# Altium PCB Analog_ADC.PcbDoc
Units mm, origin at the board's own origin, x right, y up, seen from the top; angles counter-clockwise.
Board outline 78 x 60 mm, 4 copper layers (Top Layer, GND1, Power, Bottom Layer), stack 0.603 mm thick; 92 components, 48 nets, 281 pads, 215 vias.
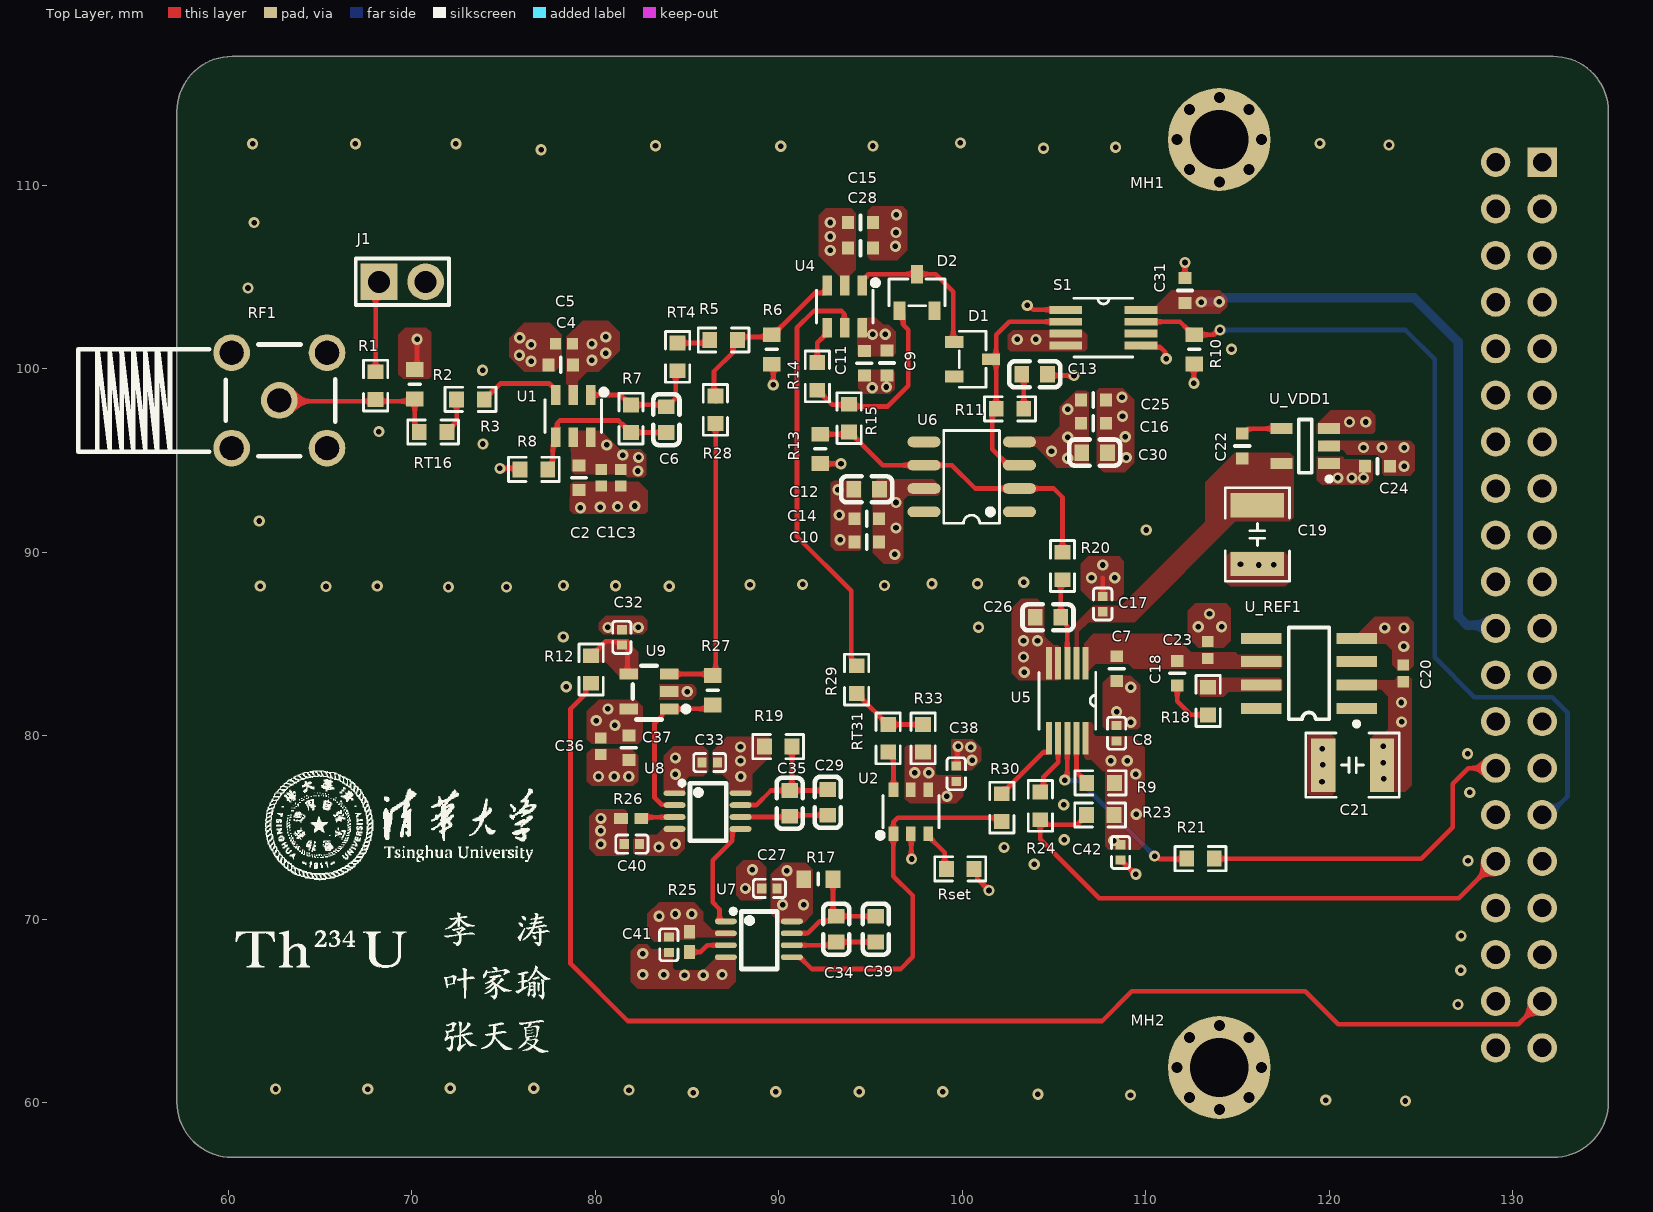
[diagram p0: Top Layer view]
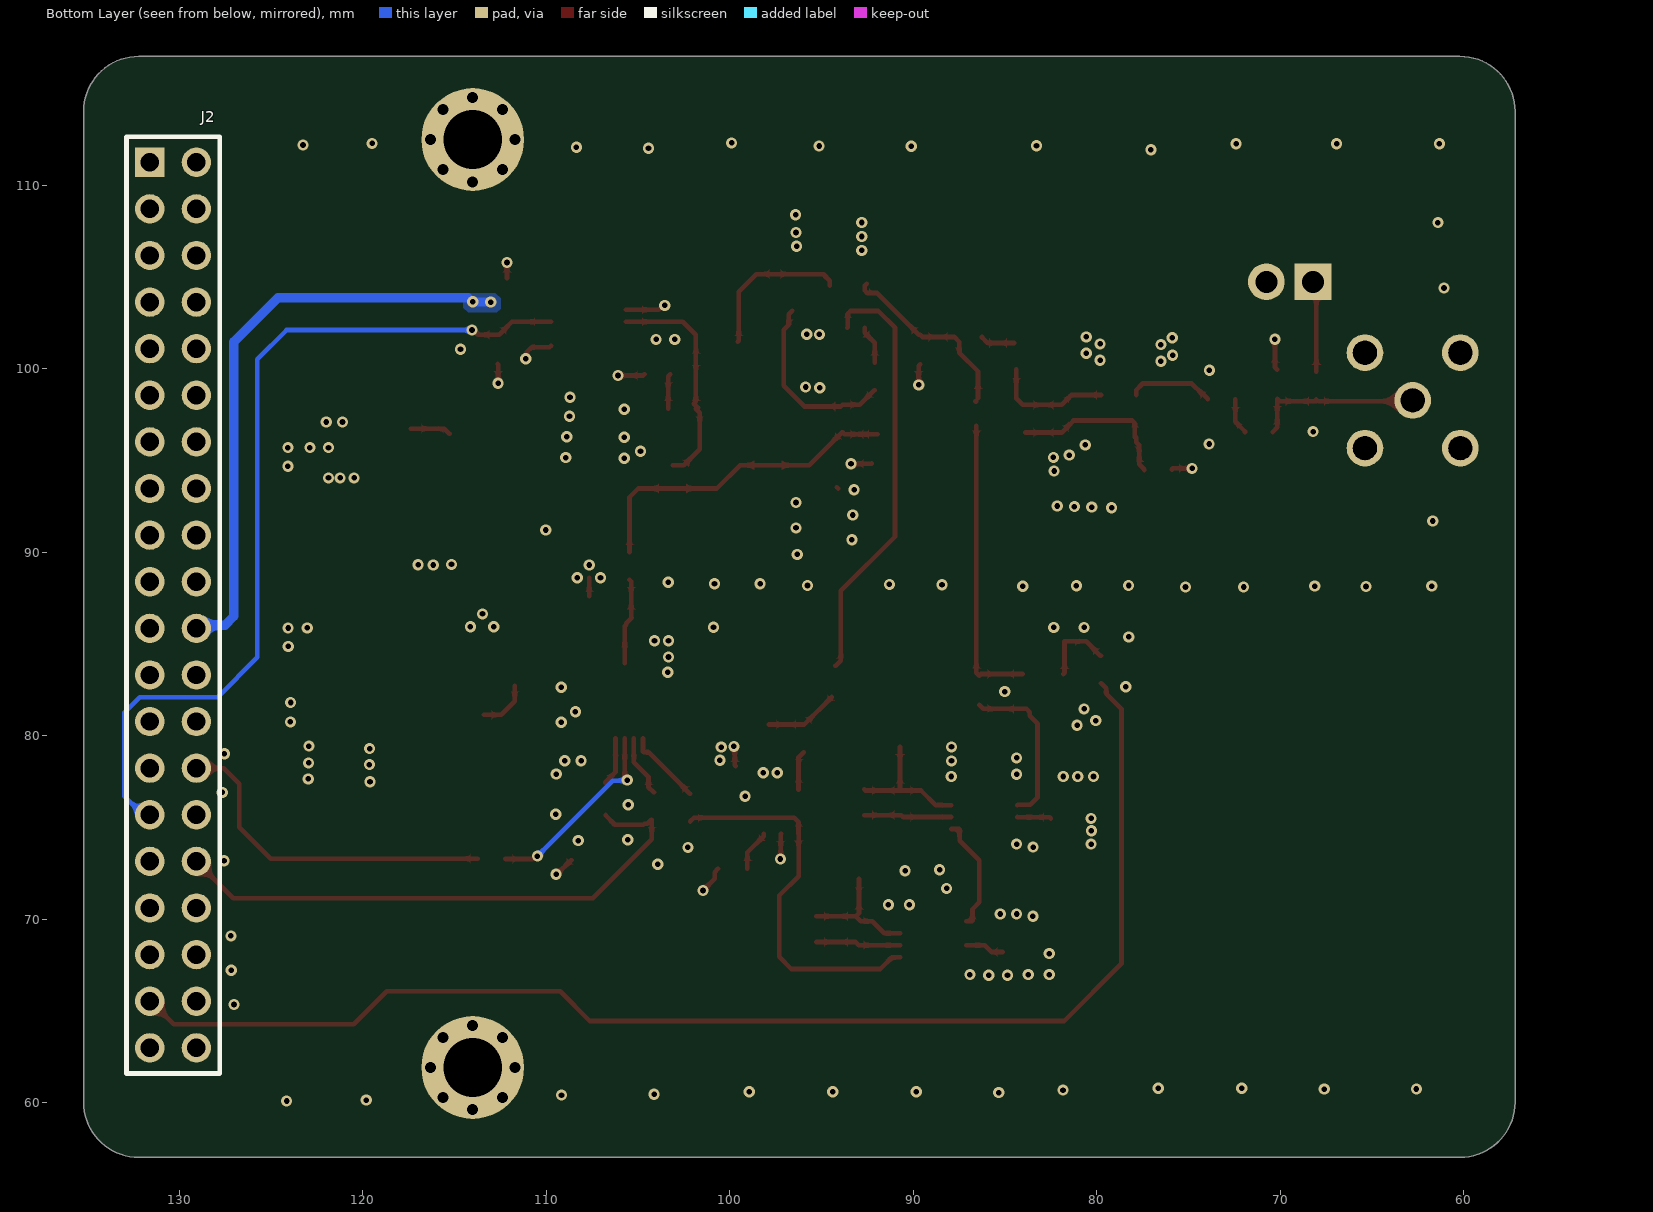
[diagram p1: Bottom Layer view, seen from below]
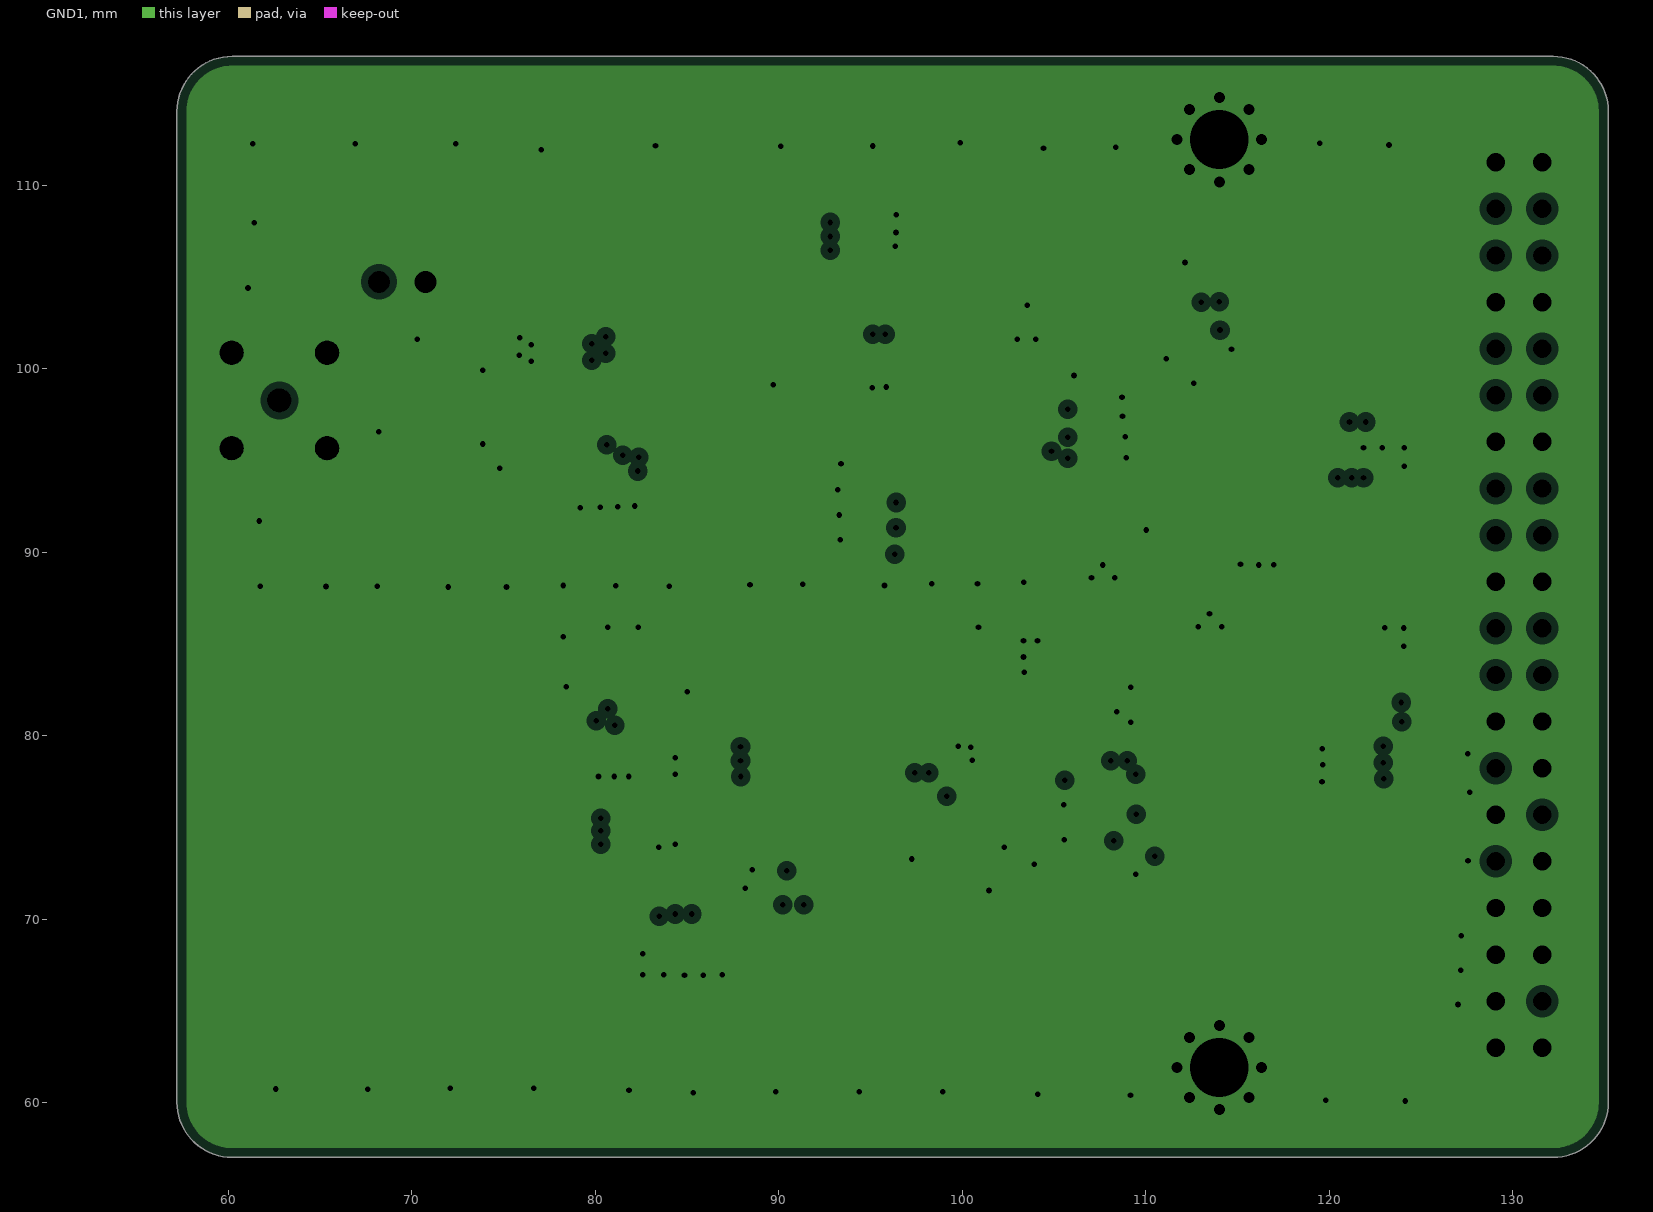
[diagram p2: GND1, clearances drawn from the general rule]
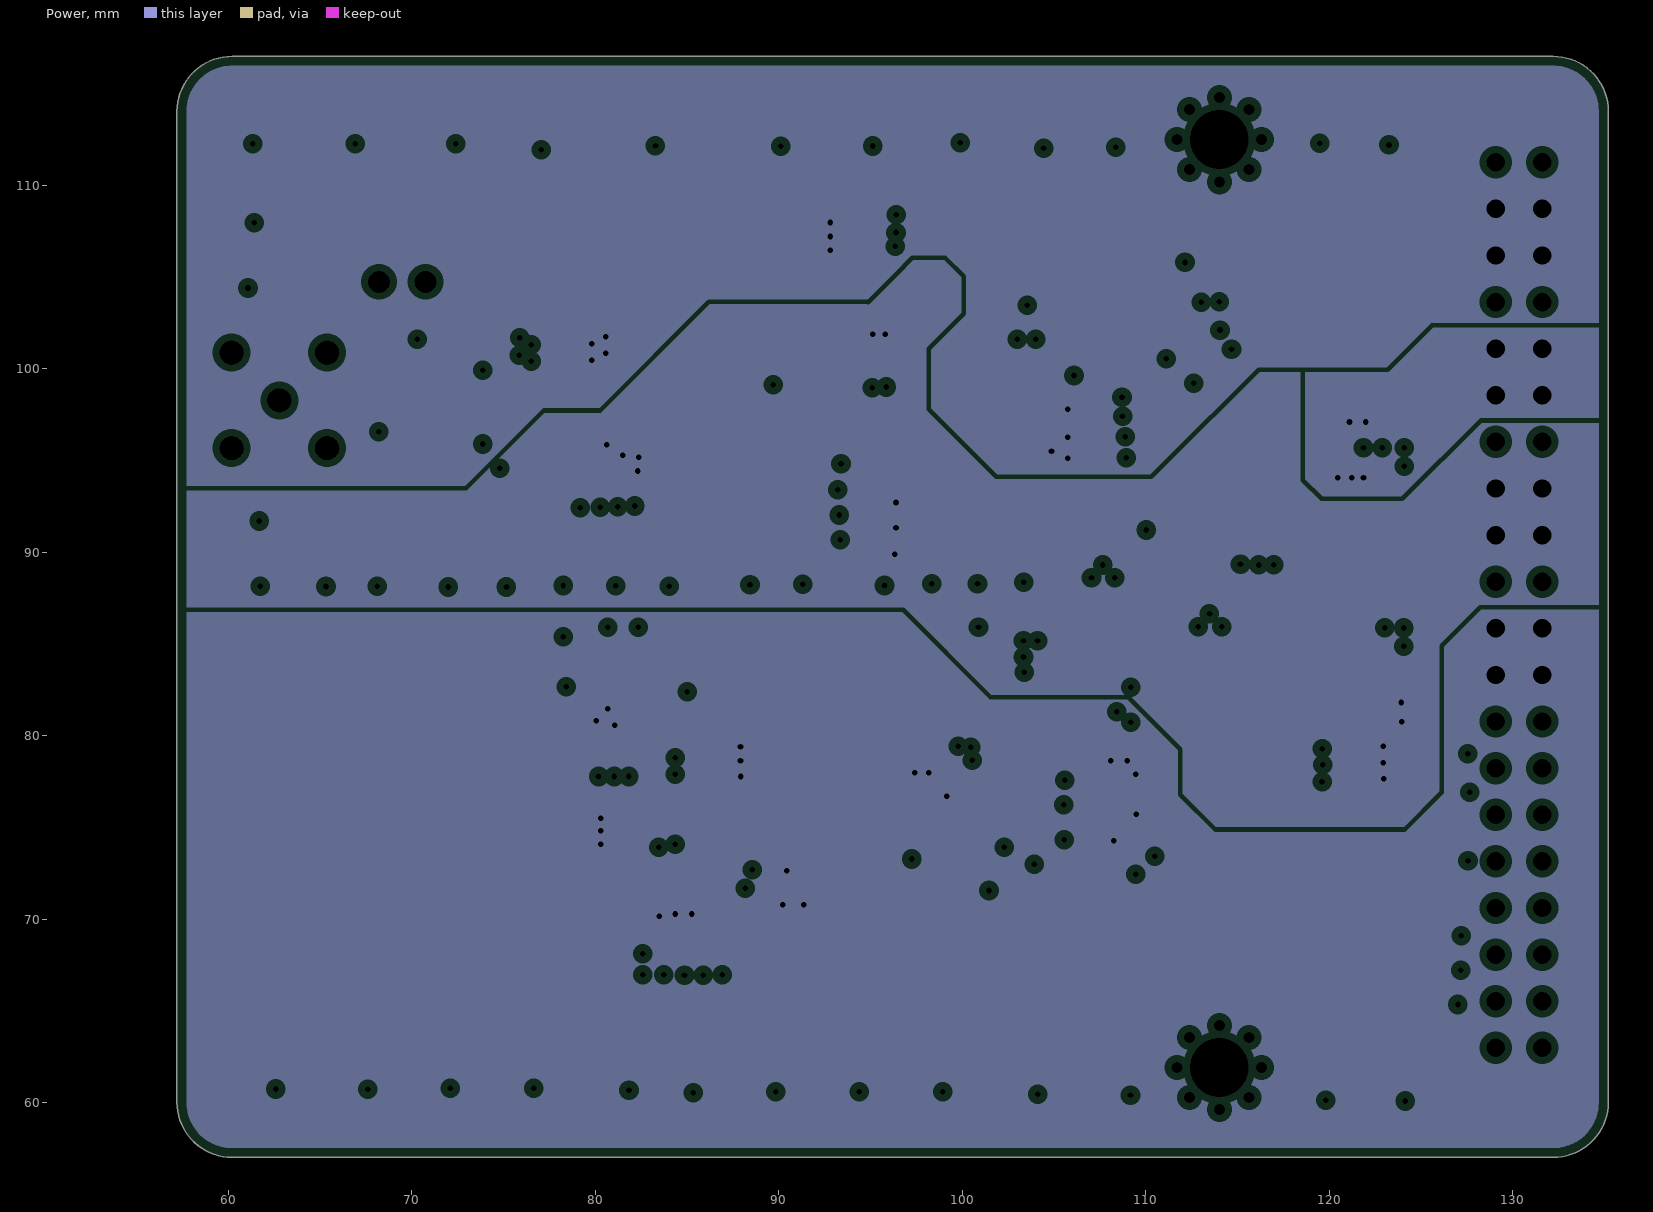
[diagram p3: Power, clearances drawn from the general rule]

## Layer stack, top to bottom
Top Solder: solder mask 0.0102, Solder Resist, Dk 3.5
Top Layer: signal copper 0.0356
Dielectric 2: prepreg 0.0711, PP-006, Dk 4.1
GND1: plane copper 0.035, net AGND
Dielectric 1: dielectric 0.32, FR-4, Dk 4.8
Power: plane copper 0.035, net (Multiple Nets)
Dielectric 3: prepreg 0.0711, PP-006, Dk 4.1
Bottom Layer: signal copper 0.0356
Bottom Solder: solder mask 0.0102, Solder Resist, Dk 3.5

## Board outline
57.207,60.023 57.207,114.023 cw(c60.207,114.023) 60.207,117.023 132.207,117.023 cw(c132.207,114.023) 135.207,114.023 135.207,60.023 cw(c132.207,60.023) 132.207,57.023 60.207,57.023 cw(c60.207,60.023)

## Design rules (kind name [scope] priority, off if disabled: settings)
Clearance [All] p1: gap=0.152 ignorepadtopadclearanceinfootprint=TRUE except(0: Arc-Hole Track-Hole SMDPad-Hole THPad-Hole Via-Hole Fill-Hole Poly-Hole Region-Hole Text-Hole)
HoleSize [All] p1: absolutevalues=TRUE maxlimit=12.7 minlimit=0.025 maxpercent=80.000 minpercent=20.000
HoleToHoleClearance [All] p1: gap=0 allowstackedmicrovias=TRUE
MinimumSolderMaskSliver [All] p1 off: minsoldermaskwidth=0
PlaneClearance [All] p1: clearance=0.381
PlaneConnect [All] p1: planeconnectstyle=Direct reliefexpansion=0.508 reliefentries=4 reliefconductorwidth=0.254 reliefairgap=0.254
PolygonConnect [All] p1: connectstyle=Direct reliefconductorwidth=0.254 reliefentries=4 polygonreliefangle="90 Angle" airgapwidth=0.254
RoutingVias [All] p1: holewidth=0.305 width=0.61 viastyle="Through Hole" minholewidth=0 minwidth=0 maxholewidth=2.54 maxwidth=2.54
SilkToSilkClearance [All] p1 off: silktosilkclearance=0
SilkToSolderMaskClearance [IsPad] p1 off: minsilkscreentomaskgap=0 clearancetoexposedcopper=TRUE
SolderMaskExpansion [All] p1: expansion=0.102 istentingtop=FALSE
Width [All] p1: maxlimit=0.762 minlimit=0.152 preferedwidth=0.254
23 further rules are at their usual default settings.

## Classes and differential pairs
component class Trigger: C27 C29 C32 C33 C34 C35 C36 C37 C38 C39 C40 C41 R12 R17 R19 R25 R26 R27 R28 R33 Rset RT31 U2 U7 U8 U9
component class Peakhold: C9 C10 C11 C12 C13 C14 C15 C16 C25 C28 C30 C31 D1 D2 R10 R11 R13 R14 R15 R29 S1 U4 U6
component class BAMP: C1 C2 C3 C4 C5 C6 R3 R5 R6 R7 R8 RT4 RT16 U1
component class Analog: C18 C19 C20 C21 C22 C23 C24 J1 J2 MH1 MH2 R1 R2 R18 RF1 U_REF1 U_VDD1
component class ADC: C7 C8 C17 C26 C42 R9 R20 R21 R23 R24 R30 U5

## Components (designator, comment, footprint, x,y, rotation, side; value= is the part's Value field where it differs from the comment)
C1 "1uF/50V" CAPC1005X70N 80.32,94.061 r90 top
C2 "100nF/100V" GRM18x 79.113,94.061 r270 top
C3 "1uF/50V" CAPC1005X70N 81.399,94.061 r90 top
C4 "100nF/100V" GRM18x 78.125,100.208 r0 top
C5 "1uF/50V" CAPC1005X70N 78.292,101.351 r0 top
C6 "15pF" C0603 83.955,97.233 r90 top
C7 "10uF/10V" GRM18x 108.418,83.655 r270 top
C8 "100nF" C0402 108.418,80.429 r270 top
C9 "1uF/25V" GRM18x 95.903,100.312 r270 top
C10 "4.7uF/25V" GRM18x 94.798,90.558 r180 top
C11 "100nF/100V" GRM18x 94.666,100.296 r270 top
C12 "470pF" C0603 94.798,93.352 r0 top
C13 "200pF" C0603 103.958,99.62 r0 top
C14 "100nF/100V" GRM18x 94.798,91.828 r180 top
C15 "1uF/25V" GRM18x 94.459,107.97 r180 top
C16 "100nF/100V" GRM18x 107.149,97.029 r180 top
C17 "100nF" C0402 107.656,86.881 r90 top
C18 "10nF/50V" GRM18x 111.72,83.401 r90 top
C19 "10uF 50V" C1210-H2r50 116.085,90.965 r270 top
C20 "100nF/50V" CAPC1005X70N 124.039,83.401 r90 top
C21 "10uF 50V" C1210-H2r50 121.271,78.4 r180 top
C22 "10nF/50V" GRM18x 115.264,95.786 r90 top
C23 "100nF/50V" CAPC1005X70N 113.371,84.671 r90 top
C24 "1uF/25V" GRM18x 122.63,94.683 r180 top
C25 "4.7uF/25V" GRM18x 107.149,98.299 r180 top
C26 "2.7nF" C0603 104.681,86.374 r0 top
C27 "100nF" C0402 89.197,71.682 r0 top
C28 "100nF/100V" GRM18x 94.459,106.573 r180 top
C29 "10pF，DNP" C0603 92.753,76.381 r90 top
C30 "470pF" C0603 107.212,95.505 r180 top
C31 "100nF/100V" GRM18x 112.141,104.267 r90 top
C32 "100nF" C0402 81.45,85.652 r270 top
C33 "100nF" C0402 85.946,78.54 r0 top
C34 "39pF NP0" C0603 93.21,69.465 r90 top
C35 "75pF" C0603 90.67,76.323 r90 top
C36 "1uF/50V" CAPC1005X70N 80.307,79.429 r90 top
C37 "100nF/100V" GRM18x 81.831,79.342 r270 top
C38 "100nF" C0402 99.674,78.221 r270 top
C39 "5pF, DNP" C0603 95.369,69.465 r90 top
C40 "100nF" C0402 81.704,74.095 r0 top
C41 "100nF" C0402 84.01,68.898 r270 top
C42 "100nF" C0402 108.63,73.348 r90 top
D1 "BAT17" SOT23-3 99.568,101.468 r180 top
D2 "BAT17" SOT23-3 96.586,103.157 r270 top
J1 "Header 2" "Header 2" 68.217,104.74 r0 top
J2 "PM2.54-2X20P-H85" "2*20 2.54mm 排母" 131.5,110.876 r270 bottom
MH1 "Mounting Hole (Screw)" MOUNT_PAD_L-M3 114.007,112.488 r0 top
MH2 "Mounting Hole (Screw)" MOUNT_PAD_L-M3 114.008,61.921 r0 top
R1 "50Ω" R0603 68.005,99.065 r270 top
R2 "1MΩ" RESC1608X55N 70.164,99.154 r270 top
R3 "22Ω" R0603 73.212,98.303 r0 top
R5 "50Ω" R0603 87.01,101.54 r0 top
R6 "1MΩ" RESC1608X55N 89.623,101.052 r90 top
R7 "470Ω" R0603 81.975,97.287 r90 top
R8 "470Ω" R0603 76.669,94.486 r0 top
R9 "0Ω" R0603 107.55,77.407 r0 top
R10 "100kΩ" RESC1608X55N 112.649,101.054 r270 top
R11 "22Ω" R0603 102.616,97.79 r0 top
R12 "1kΩ" R0603 79.799,83.62 r90 top
R13 "1MΩ" RESC1608X55N 92.26,95.637 r90 top
R14 "91Ω" R0603 92.075,99.568 r270 top
R15 "348Ω" R0603 93.813,97.295 r270 top
R17 "2kΩ" RESC1608X55N 92.156,72.19 r180 top
R18 "82kΩ" R0603 113.371,81.877 r270 top
R19 "5kΩ" R0603 89.959,79.429 r180 top
R20 "20Ω" R0603 105.491,89.262 r90 top
R21 "22Ω" R0603 112.996,73.278 r0 top
R23 "47kΩ" R0603 107.529,75.654 r0 top
R24 "22Ω" R0603 104.227,76.162 r270 top
R25 "10kΩ" RESC1005X35N 85.133,68.761 r90 top
R26 "10kΩ" RESC1005X35N 81.958,75.492 r0 top
R27 "100kΩ" RESC1608X55N 86.403,82.477 r270 top
R28 "100Ω" R0603 86.522,97.749 r270 top
R29 "50Ω" R0603 94.276,83.067 r90 top
R30 "22Ω" R0603 102.182,76.095 r90 top
R33 "47kΩ" R0603 97.896,79.872 r90 top
RF1 "HJ-SMA508" HJ-SMA508 59.931,102.911 r0 top
Rset "127kΩ" R0603 99.88,72.771 r180 top
RT4 "0Ω" R0603 84.516,100.657 r90 top
RT16 "0Ω" R0603 71.18,96.525 r0 top
RT31 "0Ω" R0603 95.991,79.872 r90 top
S1 "ADG721" RM_8 107.696,102.235 r0 top
U1 "ADA4807-1ARJZ-R2" ADA4807-1ARJZ-R2 80.491,98.947 r180 top
U2 "LTC6993-3" LTC6993-3 96.88,75.935 r270 top
U4 "ADA4807-1ARJZ-R2" ADA4807-1ARJZ-R2 95.29,104.91 r180 top
U5 "AD7980" MSOP-10 105.497,82.004 r0 top
U6 "THS4631DR" THS4631DR 101.526,92.215 r90 top
U7 "SN74LVC1G123DCTR" SSOP8 88.308,69.904 r180 top
U8 "SN74LVC1G123DCTR" SSOP8 85.514,76.889 r180 top
U9 "LMV7239QDBVRQ1" LMV7239QDBVRQ1 84.914,81.422 r0 top
U_REF1 "ADR431" SO-8 121.492,81.496 r180 top
U_VDD1 "LT1761ES5-2.5" SOT23-5 118.693,95.786 r180 top

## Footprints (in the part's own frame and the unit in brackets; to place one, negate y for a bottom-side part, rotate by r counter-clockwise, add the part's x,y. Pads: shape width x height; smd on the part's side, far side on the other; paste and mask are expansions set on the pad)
"2*20 2.54mm 排母" [mil]
  rect 63x63 hole 39.4: 1(-14.8,-4.2)
  round 63 hole 39.4: 2(-14.8,95.8) 3(85.2,-4.2) 4(85.2,95.8) 5(185.2,-4.2) 6(185.2,95.8) 7(285.2,-4.2) 8(285.2,95.8) 9(385.2,-4.2) 10(385.2,95.8) 11(485.2,-4.2) 12(485.2,95.8) 13(585.2,-4.2) 14(585.2,95.8) 15(685.2,-4.2) 16(685.2,95.8) 17(785.2,-4.2) 18(785.2,95.8) 19(885.2,-4.2) 20(885.2,95.8) 21(985.2,-4.2) 22(985.2,95.8) 23(1085.2,-4.2) 24(1085.2,95.8) 25(1185.2,-4.2) 26(1185.2,95.8) 27(1285.2,-4.2) 28(1285.2,95.8) 29(1385.2,-4.2) 30(1385.2,95.8) 31(1485.2,-4.2) 32(1485.2,95.8) 33(1585.2,-4.2) 34(1585.2,95.8) 35(1685.2,-4.2) 36(1685.2,95.8) 37(1785.2,-4.2) 38(1785.2,95.8) 39(1885.2,-4.2) 40(1885.2,95.8)
  silkscreen extent -70,-54 1940,146
ADA4807-1ARJZ-R2 [mm]
  rect 0.532x1.072 smd paste+0.051: 1(0.741,0.377) 2(1.691,0.377) 3(2.641,0.377) 4(2.641,2.675) 5(1.691,2.675) 6(0.741,2.675)
  silkscreen extent -0.13,0.07 3.23,2.42
C0402 [mil]
  rect 19.7x21.3 smd: 1(-5,0) 2(28,0)
  silkscreen extent -23,-20 46,20
C0603 [mm]
  rect 0.8x0.9 smd paste+0.051: 1(-0.707,0.075) 2(0.693,0.075)
  silkscreen extent -1.4,-0.64 1.38,0.79
C1210-H2r50 [mm]
  rect 1.321x2.921 smd paste+0 mask+0.076: 1(-1.6,0) 2(1.6,0)
  silkscreen extent -2.55,-1.75 2.55,1.75, body extent -1.6,-1.27 1.6,1.23, height 2.6
CAPC1005X70N [mm]
  rect 0.6x0.62 smd: 1(-0.46,0) 2(0.46,0)
  body extent -0.5,-0.25 0.5,0.25, height 0.5
GRM18x [mm]
  rect 0.65x0.7 smd: 1(-0.675,0) 2(0.675,0)
  silkscreen extent 0,-0.4 0,0.4, body extent -0.8,-0.45 0.8,0.45, height 0.8
"Header 2" [mm]
  rect 1.999x1.999 hole 1.199: 1(0,0)
  round 1.999 hole 1.199: 2(2.54,0)
  silkscreen extent -1.27,-1.27 3.81,1.27
HJ-SMA508 [mm]
  round 2 hole 1.3 slot 1.305 at 0 deg paste-2539.97 mask+0.051: 1(2.853,-4.637) 2(0.253,-2.037) 3(0.253,-7.237) 4(5.453,-7.237) 5(5.453,-2.037)
  silkscreen extent -8.1,-7.69 5.9,-1.59
LMV7239QDBVRQ1 [mm] "SOT23-5"
  rect 1.001x0.599 smd paste+0 mask+0.051: 1(-0.883,0.039) 2(-0.883,0.989) 3(-0.883,1.939) 4(-3.083,1.939) 5(-3.083,0.039)
  silkscreen extent -2.87,-0.54 0.18,2.39
LTC6993-3 [mil]
  rect 31.5x20.9 smd: 1(50.2,-24.74) 2(50.2,12.66) 3(50.2,50.06) 4(-44.3,50.06) 5(-44.3,12.66) 6(-44.3,-24.74)
  silkscreen extent -32,-59 60,73
MOUNT_PAD_L-M3 [mm]
  round 5.6 hole 3.2: 1(0,0)
MSOP-10 [mil]
  rect 13x70 smd: 1(48.37,76.5) 2(28.68,76.5) 3(9,76.5) 4(-10.69,76.5) 5(-30.37,76.5) 6(-30.37,-84.5) 7(-10.69,-84.5) 8(9,-84.5) 9(28.68,-84.5) 10(48.37,-84.5)
  silkscreen extent -52,-65 70,57, body extent -50,-105 68,88, height 45
R0603 [mm]
  rect 0.806x0.864 smd paste-100 mask+0.051: 1(-0.765,0.026) 2(0.741,0.026)
  silkscreen extent -1.4,-0.64 1.37,0.69
RESC1005X35N [mm]
  rect 0.75x0.6 smd: 1(-0.55,0) 2(0.55,0)
  body extent -0.5,-0.25 0.5,0.25, height 0.35
RESC1608X55N [mm]
  rect 0.8x0.95 smd: 1(-0.8,0) 2(0.8,0)
  silkscreen extent 0,-0.3 0,0.3, body extent -0.8,-0.4 0.8,0.4, height 0.55
RM_8 [mil]
  rect 70x17 smd mask+4: 1(-80.5,38.39) 2(-80.5,12.8) 3(-80.5,-12.8) 4(-80.5,-38.39) 5(80.5,-38.39) 6(80.5,-12.8) 7(80.5,12.8) 8(80.5,38.39)
  silkscreen extent -63,-63 63,63, body extent -102,-63 102,63, height 43
SO-8 [mm]
  rect 2.2x0.6 smd: 1(0,0) 2(0,-1.27) 3(0,-2.54) 4(0,-3.81) 5(5.2,-3.81) 6(5.2,-2.54) 7(5.2,-1.27) 8(5.2,0)
  silkscreen extent -0.12,-4.4 3.7,0.97, body extent -0.63,-4.42 5.71,0.58, height 1.88
SOT23-3 [mm]
  rect 1.001x0.65 smd: 1(0,0) 2(0,1.9) 3(-1.999,0.95)
  silkscreen extent -1.72,-0.58 -0.27,2.48
SOT23-5 [mm] "SOT23, for LT1964, 5-Leads, Body 2.9x2.8mm (max), Pitch 0.95mm, IPC Medium Density"
  rect 1.2x0.6 smd: 1(-1.3,0.95) 2(-1.3,0) 3(-1.3,-0.95) 4(1.3,-0.95) 5(1.3,0.95)
  silkscreen extent -1.43,-1.45 0.35,1.92, body extent -1.37,-1.46 0.97,1.46, height 1
SSOP8 [mm] "SN74"
  oval 1.196x0.315 smd: 1(1.189,0.021) 2(1.189,0.671) 3(1.189,1.321) 4(1.189,1.971) 5(-2.408,1.971) 6(-2.408,1.321) 7(-2.408,0.671) 8(-2.408,0.021)
  silkscreen extent -1.62,-0.66 0.91,2.62
THS4631DR [mil]
  oval 23.1x70.9 smd paste+0 mask+2: 1(-0.5,-62.6) 2(49.5,-62.6) 3(99.5,-62.6) 4(149.5,-62.6) 5(149.5,142.1) 6(99.5,142.1) 7(49.5,142.1) 8(-0.5,142.1)
  silkscreen extent -25,-20 174,100

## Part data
C1 C3 C5 C36: library part GRM155R61H105KE05D, "1uF 10% 50V 0402 X5R", Arrow Part Number=GRM155R61E105KA12D, Manufacturer_Name="Murata Electronics", Mouser Part Number=81-GRM155R61E105KA2D
C2 C4 C11 C14 C16 C28 C31 C37: library part GCM188R72A104KA64D, "100nF 10% 100V X7R 0603", Arrow Part Number=GRM188Z71A106KA73D, Manufacturer_Name="Murata Electronics", Mouser Part Number=81-GRM188Z71A106KA3D
C6: library part CC0603FRNPO9BN150, "15pF ±1% 50V 0603 NP0"
C7: library part GRM188Z71A106KA73D, "10uF 10% 10V X7R 0603", Manufacturer_Name="Murata Electronics", Mouser Part Number=81-GRM188Z71A106KA3D
C8 C17 C27 C32 C33 C38 C40 C41 C42: library part GCM155R71H104KE02D, "100nF ±10% 50V 0402 GCM"
C9 C15 C24: library part GCM188R71E105KA64D, "1uF 10% 25V X7R 0603", Arrow Part Number=GRM188Z71A106KA73D, Manufacturer_Name="Murata Electronics", Mouser Part Number=81-GRM188Z71A106KA3D
C10 C25: library part GRT188C81E475KE13D, "4.7uF 10% 25V 0603 X6S", Manufacturer_Name="Murata Electronics", Manufacturer_Part_Number=GRM155C71H683KE19D, Mouser Part Number=81-GRM155C71H683KE9D
C12 C30: library part CC0603KRX7R9BB471, "470pF ±10% 50V 0603 X7R"
C13: library part GCM1885C2A201FA16J, "200pF ±1% 100V 0603"
C18 C22: library part GCM1885C1H103GA16D, "10nF 2% 50V 0603 C0G", Manufacturer_Name="Murata Electronics", Manufacturer_Part_Number=GRM155C71H683KE19D, Mouser Part Number=81-GRM155C71H683KE9D
C19 C21: library part GRM32ER71H106KA12L, "10uF 50V 10% 1210 X7R"
C20 C23: library part GCM155R71H104KE02D, "100nF 10% 50V 0402 X7R", Manufacturer_Name="Murata Electronics", Manufacturer_Part_Number=GRM155C71H683KE19D, Mouser Part Number=81-GRM155C71H683KE9D
C26: library part CC0603KRX7R9BB272, "2.7nF ±10% 50V 0603 X7R"
C29: library part GCM1885C2A100FA16D, "10pF ±1% 100V 0603"
C34: library part CC0603JRNPO9BN390, "39pF ±5% 50V NP0"
C35: library part GQM1875C2E750FB12D, "75pF ±1% 250V 0603 C0G"
C39: library part GCM1885C1H5R0CA16D, "±0.25pF 5pF 50V 0603"
D1 D2: "电压:4V 电流:30mA"
J1: "1x2P 间距:2.54mm 方针 直插"
J2: "2*20 排母"
MH1 MH2: library part Mounting-Hole-Screw_1, "Mounting Hole, M3 Screw"
R1 R5 R29: library part RT0603BRE0750RL, "薄膜电阻 50Ω ±0.1% 100mW 0603"
R2 R6 R13: library part RT0603BRD071ML, "1MΩ 0.1% 0603 100mW 薄膜 25ppm/℃ 工作电压75V", Manufacturer_Name=YAGEO, Manufacturer_Part_Number=RT0603BRD07523KL
R3 R11 R21 R24 R30: library part RT0603BRE0722RL, "薄膜电阻 22Ω ±0.1% 100mW 0603"
R7 R8: library part RT0603BRB07470RL, "薄膜电阻 470Ω ±0.1% 100mW 0603"
R9 RT4 RT16 RT31: library part PMR03EZPJ000, "厚膜电阻 0Ω 250mW 0603"
R10 R27: library part RT0603BRD07100KL, "100kΩ 0.1% 0603 100mW 薄膜 25ppm/℃", Manufacturer_Name=YAGEO, Manufacturer_Part_Number=RT0603BRD07523KL
R12: library part RT0603BRD071KL, "薄膜电阻 1kΩ ±0.1% 100mW 0603"
R14: library part RT0603BRE0791RL, "薄膜电阻 91Ω ±0.1% 100mW 0603"
R15: library part TD03G3480BT, "薄膜电阻 348Ω ±0.1% 100mW 0603 FH"
R17: library part RT0603BRD072KL, "2kΩ 0.1% 0603 100mW 薄膜 25ppm/℃", Manufacturer_Name=YAGEO, Manufacturer_Part_Number=RT0603BRD07523KL
R18: library part RT0603BRD0782KL, "薄膜电阻 82kΩ ±0.1% 100mW 0603"
R19: library part RT0603BRE075KL, "薄膜电阻 5kΩ ±0.1% 100mW 0603"
R20: library part RT0603BRD0720RL, "薄膜电阻 20Ω ±0.1% 100mW 0603"
R23 R33: library part RT0603FRD0747KL, "薄膜电阻 47kΩ ±1% 100mW 0603"
R25 R26: library part RT0402BRD0710KL, "10kΩ 0.1% 0402 62.5mW 薄膜 25ppm/℃", Manufacturer_Name=YAGEO, Manufacturer_Part_Number=RT0402BRD07100RL, Mouser Part Number=603-RT0402BRD07100RL
R28: library part RT0603BRD07100RL, "薄膜电阻 100Ω ±0.1% 100mW"
Rset: library part RT0603DRE07127KL, "薄膜电阻 127kΩ ±0.5% 100mW 0603"
S1: library part ADG72x
U2: "下降沿触发单稳态触发器"
U5: "16-Bit, 1 MSPS PulSAR ADC in MSOP/QFN"
U6: "高压，高 slew rate，宽带 FET 输入运算放大器"
U7 U8: "单稳态多谐振荡器"
U_REF1: library part ADR43x
U_VDD1: library part LT1761-fix, "Low Noise LDO (100mA)-> 1.2~3.3V~5V, or Adj<20V"

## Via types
v1: diameter 0.61, hole 0.305, Top Layer to Bottom Layer, 199 vias
v2: diameter 1, hole 0.6, Top Layer to Bottom Layer, 16 vias

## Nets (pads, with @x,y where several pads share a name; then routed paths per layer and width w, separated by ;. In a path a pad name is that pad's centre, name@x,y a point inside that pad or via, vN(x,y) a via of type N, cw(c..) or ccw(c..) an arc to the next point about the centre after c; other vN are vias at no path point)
+2.5VA_REF: C7.1 C18.2 C23.1 U5.1 U_REF1.6
+2.5VA_VDD: C17.1 C19.1 C22.1 U5.2 U_VDD1.5
+3V3: C8.2 C27.2 C31.1 C33.2 C36.2 C37.1 C38.2 C40.1 C41.1 C42.2 J2.21 J2.22 J2.23 J2.24 R9.2 R17.2 R19.2 R23.2 R25.2 R26.1 R33.1 S1.8 U2.4 U2.5 U5.10 U7.2 U7.8 U8.8 U9.5 | length 32.4
  Bottom Layer w0.508: v1(113.03,103.632) v1@114.011,103.632 ; v1(114.011,103.648) 114.038,103.648 114.262,103.872 124.615,103.872 127.024,101.463 127.024,86.507 127.505,86.027 128.892,86.027 J2.22
  other v1: 83.482,70.158 84.371,70.285 85.26,70.285 90.213,70.793 91.356,70.793 90.443,72.643 80.307,74.095 108.259,74.285 80.295,74.82 80.307,75.492 109.482,75.716 99.166,76.697 87.927,77.778 109.454,77.911 97.417,77.987 98.179,77.987 87.915,78.63 108.102,78.631 108.991,78.631 87.915,79.392 81.069,80.572 80.053,80.826 80.688,81.461
+5V: C24.2 J2.9 J2.10 J2.11 J2.12 U_VDD1.1 U_VDD1.3
  other v1: 120.471,94.048 121.233,94.048 121.868,94.048 121.106,97.096 121.995,97.096
+5VA: C1.2 C2.1 C3.2 C9.1 C10.1 C11.1 C12.2 C14.1 C20.1 C21.1 J2.15 J2.16 J2.17 J2.18 U1.5 U1.6 U4.6 U6.7 U_REF1.2
  other v1: 122.968,77.645 122.949,78.519 122.936,79.434 123.947,80.755 123.93,81.81 96.32,89.883 96.392,91.326 96.393,92.71 82.323,94.426 82.365,95.167 81.501,95.295 80.625,95.848 95.117,101.869 95.803,101.875
-5VA: C4.2 C5.2 C15.2 C16.2 C25.2 C28.2 C30.2 J2.3 J2.4 J2.5 J2.6 U1.2 U4.2 U6.4
  other v1: 105.752,95.124 104.863,95.505 105.752,96.267 105.752,97.791 79.816,100.462 80.578,100.843 79.816,101.351 80.578,101.732 92.808,106.446 92.808,107.208 92.808,107.97
ADC_CNV: R30.1 U2.1 U7.5 | length 21
  Top Layer w0.254: U7.5 91.157,67.933 91.801,67.288 96.639,67.288 97.306,67.956 97.306,71.292 96.248,72.35 96.248,74.656 U2.1 96.251,75.293 96.493,75.535 101.951,75.535 R30.1
ADC_SCK: J2.28 R21.2 | length 18.8
  Top Layer w0.254: R21.2 125.01,73.304 126.726,75.02 126.726,77.389 127.569,78.232 J2.28
ADC_SDO: J2.32 R23.1 R24.2 | length 30.9
  Top Layer w0.254: R24.2 104.253,74.35 107.456,71.148 127.062,71.148 J2.32 ; R24.2@104.282,75.421 104.494,75.208 104.647,75.208 104.707,75.149 106.262,75.149 106.764,75.651 R23.1
AGND: C1.1 C2.2 C3.1 C4.1 C5.1 C7.2 C8.1 C9.2 C10.2 C11.2 C12.1 C13.2 C14.2 C15.1 C16.1 C17.2 C19.2 C20.2 C21.2 C23.2 C24.1 C25.1 C26.1 C27.1 C28.1 C30.1 C31.2 C32.1 C33.1 C36.1 C37.2 C38.1 C40.2 C41.2 C42.1 J1.2 J2.1 J2.2 J2.7 J2.8 J2.13 J2.14 J2.19 J2.20 J2.25 J2.26 J2.27 J2.30 J2.31 J2.33 J2.34 J2.35 J2.36 J2.38 J2.39 J2.40 MH1.1 MH2.1 R2.1 R6.1 R8.1 R10.2 R13.1 RF1.2 RF1.3 RF1.4 RF1.5 Rset.1 S1.1 S1.3 S1.4 S1.5 U2.2 U5.4 U5.5 U7.4 U8.1 U8.4 U9.2 U_REF1.4 U_VDD1.2 | length 19.8
  Top Layer w0.254: R2.1 70.291,100.081 v1(70.291,101.605) ; v1(74.806,94.568) 75.848,94.568 R8.1 ; R6.1 89.706,100.169 v1(89.706,99.118) ; R13.1 92.281,94.817 v1(93.394,94.817) ; C12.1@94.087,93.472 C12.1@94.162,93.547 ; U2.2 97.22,74.641 97.22,73.3 v1(97.238,73.281) ; C38.1 99.724,78.398 99.724,79.367 v1(99.774,79.417) ; Rset.1 100.827,72.563 100.827,72.198 v1(101.461,71.564) ; v1(103.547,103.451) 103.643,103.451 103.883,103.21 S1.1 ; C13.2 104.716,99.63 v1(106.091,99.63) ; 107.652,88.615 107.654,88.612 107.654,87.595 C17.2 ; C42.1 108.65,73.221 109.417,72.454 v1(109.466,72.454) ; S1.5 109.826,101.174 110.791,101.174 111.049,100.916 111.049,100.607 v1(111.117,100.539) ; C31.2 v1(112.141,105.791) ; v1(112.623,99.211) 112.623,100.228 R10.2 ; J2.30@128.843,75.468 J2.30
  Bottom Layer w0.254: J2.38@128.804,65.532 J2.38 ; J2.26@129.067,80.408 J2.26
  other v1: 124.148,60.093 119.811,60.142 109.169,60.414 104.122,60.46 85.34,60.551 89.842,60.596 94.39,60.596 98.937,60.596 81.839,60.687 62.579,60.749 67.6,60.744 72.102,60.79 76.649,60.79 127.015,65.354 84.867,66.946 85.883,66.946 82.593,66.983 83.736,66.983 86.911,66.983 127.169,67.223 82.593,68.126 127.188,69.089 88.181,71.682 88.562,72.698 103.921,72.995 127.562,73.183 102.285,73.915 83.47,73.931 84.371,74.095 105.562,74.327 105.536,76.233 127.661,76.913 119.609,77.495 80.18,77.778 81.035,77.778 81.831,77.778 84.371,77.905 119.637,78.425 100.541,78.668 84.371,78.794 127.539,79.021 119.628,79.298 100.46,79.379 109.18,80.734 108.413,81.311 85.017,82.404 109.18,82.639 78.423,82.668 103.379,83.461 103.338,84.29 124.058,84.869 103.338,85.179 104.1,85.179 78.257,85.388 123.022,85.878 124.07,85.869 80.688,85.906 82.339,85.906 100.886,85.911 112.863,85.941 114.133,85.941 113.473,86.639 71.999,88.106 75.163,88.106 65.327,88.131 84.031,88.148 61.746,88.152 68.119,88.156 81.107,88.168 78.265,88.188 95.765,88.188 88.436,88.229 91.299,88.249 98.349,88.282 100.831,88.282 103.357,88.36 107.045,88.608 108.315,88.608 107.655,89.306 116.164,89.306 115.166,89.335 116.983,89.321 93.345,90.678 110.032,91.21 61.69,91.701 93.302,92.03 79.191,92.427 80.274,92.461 81.221,92.483 82.158,92.517 93.225,93.404 124.078,94.683 108.938,95.154 121.868,95.699 122.884,95.699 124.078,95.699 73.879,95.897 108.882,96.292 68.213,96.571 108.736,97.41 108.707,98.442 95.093,98.963 95.87,99.006 73.864,99.914 76.506,100.403 75.87,100.732 114.676,101.062 76.506,101.316 102.997,101.6 104.013,101.6 75.885,101.689 61.078,104.398 96.356,106.675 96.392,107.421 61.407,107.963 96.414,108.394 77.052,111.93 104.431,112.013 108.359,112.066 90.11,112.119 83.282,112.151 95.135,112.136 123.258,112.194 61.328,112.262 66.93,112.262 72.41,112.262 119.494,112.279 99.899,112.304
  other v2: 114.008,59.621 112.382,60.294 115.634,60.294 111.708,61.921 116.308,61.921 112.382,63.547 115.634,63.547 114.008,64.221 114.007,110.188 112.381,110.862 115.634,110.862 111.707,112.488 116.307,112.488 112.381,114.115 115.634,114.115 114.007,114.788
NetC6_1: C6.1 R7.1 R8.2 U1.4 | length 9
  Top Layer w0.254: R8.2@77.411,94.483 R8.2 ; R8.2@77.413,94.526 77.689,94.802 77.689,95.841 77.85,96.001 U1.4 ; U1.4@77.926,96.271 77.926,97.028 78.075,97.177 81.266,97.177 81.92,96.522 83.877,96.522 C6.1
NetC6_2: C6.2 R7.2 RT4.1 U1.1 | length 6.6
  Top Layer w0.254: U1.1 81.38,98.57 81.92,98.029 R7.2 84.033,98.029 84.385,98.38 RT4.1@84.385,99.98
NetC13_1: C13.1 R11.2 | length 1.9
  Top Layer w0.254: C13.1 103.357,99.589 R11.2
NetC18_1: C18.1 R18.2 | length 2.8
  Top Layer w0.254: C18.1 111.72,81.877 112.462,81.136 R18.2
NetC22_2: C22.2 U_VDD1.4 | length 2.2
  Top Layer w0.254: C22.2 115.289,96.461 115.564,96.736 U_VDD1.4
NetC26_2: C26.2 R20.1 U5.3 | length 4.7
  Top Layer w0.254: C26.2@105.349,86.424 105.647,86.126 105.647,86.057 105.726,85.977 U5.3 ; C26.2 105.374,88.404 R20.1
NetC29_1: C29.1 C35.1 U8.6 | length 4.8
  Top Layer w0.254: U8.6 90.546,75.568 C35.1 90.652,75.674 C29.1
NetC29_2: C29.2 C35.2 R19.1 U8.7 | length 7.6
  Top Layer w0.254: U8.7 88.781,76.218 89.578,77.016 C35.2 ; R19.1 90.725,77.146 C35.2 ; C29.2 92.621,77.016 C35.2
NetC32_2: C32.2 R12.2 U9.4 | length 4.1
  Top Layer w0.254: R12.2 79.803,84.362 80.585,85.144 81.755,85.144 81.755,84.89 81.755,83.437 U9.4
NetC34_1: C34.1 C39.1 U7.6 | length 4.6
  Top Layer w0.254: U7.6 92.959,68.583 C34.1 C39.1
NetC34_2: C34.2 C39.2 R17.1 U7.7 | length 7.1
  Top Layer w0.254: U7.7 91.575,69.233 92.226,69.885 92.861,69.885 C34.2 ; R17.1 92.956,70.336 C34.2 ; C39.2 C34.2
NetD1_1: D1.1 D2.3 U4.1 | length 8.5
  Top Layer w0.254: U4.1 94.549,104.803 94.902,105.156 98.552,105.156 99.512,104.196 99.512,101.524 D1.1
NetD1_3: D1.3 R11.1 S1.2 U6.3 | length 12.4
  Top Layer w0.254: R11.1@101.727,97.865 101.764,97.902 101.957,98.095 101.849,98.204 101.849,100.518 101.849,101.153 101.849,101.849 102.56,102.56 S1.2 ; R11.1 101.636,97.601 101.636,95.615 102.509,94.742 U6.3
NetD2_1: D2.1 R14.2 R15.1 | length 10.1
  Top Layer w0.254: R14.2 92.129,98.827 92.912,98.044 93.853,98.044 93.953,97.944 95.942,97.944 97.064,99.066 97.064,102.113 96.784,102.393 96.784,102.959 D2.1
NetR3_1: R3.1 RT16.2 | length 2
  Top Layer w0.254: RT16.2 71.921,96.58 72.447,97.105 R3.1
NetR3_2: R3.2 U1.3 | length 4.7
  Top Layer w0.254: R3.2 73.953,98.358 74.229,98.634 74.258,98.634 74.817,99.192 77.497,99.192 77.85,98.84 U1.3
NetR5_1: R5.1 RT4.2 | length 1.9
  Top Layer w0.254: RT4.2 85.922,101.398 85.951,101.427 85.98,101.427 86.256,101.703 R5.1@86.256,101.732
NetR5_2: R5.2 R6.2 R28.1 U4.3 | length 10.3
  Top Layer w0.254: R28.1@86.474,98.385 86.474,99.866 87.487,100.879 87.487,101.456 87.763,101.732 89.503,101.732 R6.2 89.698,101.852 91.97,104.124 92.51,104.124 92.649,104.263 U4.3 U4.3@92.544,104.638 ; R28.1@86.585,98.204 R28.1@86.613,98.233
NetR9_1: R9.1 U5.9 | length 2.7
  Top Layer w0.254: U5.9 106.226,78.02 106.785,77.461 R9.1
NetR13_2: R13.2 R15.2 R20.2 U6.2 U6.6 | length 18
  Top Layer w0.254: R13.2@91.948,96.431 93.747,96.431 93.853,96.537 93.882,96.537 95.677,94.742 U6.6 99.441,94.742 100.711,93.472 U6.2 104.981,93.472 105.465,92.988 R20.2
NetR14_1: R14.1 U4.4 | length 2.1
  Top Layer w0.254: R14.1 92.101,101.417 92.649,101.965 U4.4
NetR18_1: R18.1 U_REF1.7
NetR21_1: R21.1 U5.8 | length 10.8
  Top Layer w0.254: v1(105.585,77.584) 105.585,77.68 105.726,77.82 U5.8 ; v1(110.482,73.44) 110.578,73.44 110.741,73.278 112.205,73.278 R21.1
  Bottom Layer w0.254: v1(105.585,77.584) 105.614,77.555 106.367,77.555 v1(110.482,73.44)
NetR24_1: R24.1 U5.7 | length 3.4
  Top Layer w0.254: R24.1@104.126,76.928 104.155,76.928 104.431,77.204 104.431,77.752 105.226,78.547 U5.7
NetR25_1: R25.1 U7.3 | length 2.1
  Top Layer w0.254: R25.1 85.726,68.211 86.098,68.583 U7.3
NetR26_2: R26.2 U8.3 | length 1.8
  Top Layer w0.254: R26.2 82.573,75.556 84.314,75.556 U8.3
NetR27_1: R27.1 R28.2 U9.3 | length 16.1
  Top Layer w0.254: U9.3 86.32,83.361 R27.1 86.562,83.436 R28.2@86.562,96.896
NetR29_1: R29.1 R33.2 RT31.2 | length 4
  Top Layer w0.254: R29.1@94.441,82.108 95.936,80.613 RT31.2 R33.2
NetR29_2: R29.2 U4.5 | length 23.6
  Top Layer w0.254: U4.5 93.57,102.264 93.57,102.997 93.422,103.145 91.901,103.145 90.992,102.236 90.992,90.856 93.945,87.903 93.945,84.085 94.221,83.809 R29.2
NetR30_2: R30.2 U5.6 | length 4.3
  Top Layer w0.254: R30.2 102.185,76.836 102.461,77.112 102.461,77.141 104.416,79.096 104.688,79.096 104.726,79.134 U5.6
NetRset_2: Rset.2 U2.3 | length 2.3
  Top Layer w0.254: U2.3 98.151,74.525 99.039,73.638 Rset.2@99.039,72.76
NetRT31_1: RT31.1 U2.6 | length 2.2
  Top Layer w0.254: RT31.1 95.975,79.106 96.251,78.83 U2.6
Q_DELAY: U7.1 U8.5 | length 6.4
  Top Layer w0.254: U7.1 86.801,69.884 86.773,69.912 86.773,70.551 86.403,70.92 86.403,73.206 87.472,74.274 87.472,74.89 87.5,74.918 U8.5
Restart: J2.29 R10.1 S1.7 | length 48.2
  Top Layer w0.254: S1.7 111.868,102.56 112.574,101.854 R10.1 113.696,101.854 113.95,102.108 v1(114.046,102.108)
  Bottom Layer w0.254: v1(114.046,102.108) 124.156,102.108 125.742,100.523 125.742,84.269 127.908,82.103 132.146,82.103 132.988,81.261 132.988,76.693 132.603,76.309 132.588,76.309 131.971,75.692 J2.29
Sig_in: R1.2 R2.2 RF1.1 RT16.1 | length 9
  Top Layer w0.254: RF1.1@63.162,98.226 67.932,98.226 R1.2 ; R1.2@68.03,98.226 70.035,98.226 R2.2 70.164,96.802 RT16.1
Threshold: J2.37 R12.1 | length 71.9
  Top Layer w0.254: R12.1 79.755,82.855 79.479,82.579 79.479,82.284 78.656,81.461 78.656,67.579 81.781,64.455 107.628,64.455 109.248,66.075 118.682,66.075 120.484,64.273 130.3,64.273 131.559,65.532 J2.37
TRIG_RAW: R27.2 U8.2 U9.1 | length 9
  Top Layer w0.254: U8.2 84.314,76.23 83.634,76.23 83.228,76.635 83.228,80.659 83.658,81.088 83.658,81.288 83.83,81.461 86.187,81.461 R27.2
Z50: J1.1 R1.1 | length 5.6
  Top Layer w0.254: J1.1@67.608,104.13 J1.1 ; R1.1 J1.1@68.03,104.552
pads on no net: D1.2 D2.2 S1.6 U6.1 U6.5 U6.8 U_REF1.1 U_REF1.3 U_REF1.5 U_REF1.8

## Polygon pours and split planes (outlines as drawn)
AGND on Top Layer "AGND_L01_P084" (solid, remove dead copper, pour order 84): 120.43,85.581 121.594,85.581 122.488,86.475 124.306,86.475 124.6,86.181 124.6,83.804 124.365,83.569 123.741,83.569 123.43,83.881 123.43,84.669 123.424,84.669 123.059,85.034 123.047,85.022 120.453,85.022
AGND on Top Layer "AGND_L01_P082" (solid, remove dead copper, pour order 82): 118.924,80.083 118.693,79.853 118.693,77.02 118.945,76.768 120.151,76.768 120.34,76.957 120.34,79.853 120.12,80.073
+5VA on Top Layer "+5VA_L01_P081" (solid, remove dead copper, pour order 81): 120.48,83.055 120.509,83.025 123.536,83.025 123.743,83.233 124.347,83.233 124.515,83.065 124.505,83.055 124.505,77.299 124.139,76.933 122.28,76.933 122.28,79.9 122.557,80.177 123.041,80.177 123.229,80.365 123.229,82.125 122.824,82.531 120.727,82.531
AGND on Top Layer "AGND_L01_P080" (solid, remove dead copper, pour order 80): 114.638,90.023 114.396,89.781 114.396,88.339 114.597,88.137 117.592,88.137 117.773,88.319 117.763,88.329 117.763,89.821 117.551,90.033
AGND on Top Layer "AGND_L01_P007" (solid, remove dead copper, pour order 7): 95.094,108.859 94.84,108.605 94.84,106.077 95.003,105.914 96.46,105.914 96.999,106.453 96.999,108.605 96.745,108.859
-5VA on Top Layer "-5VA_L01_P006" (solid, remove dead copper, pour order 6): 93.824,104.502 93.824,105.025 94.205,105.406 94.205,108.478 93.951,108.732 92.554,108.732 92.173,108.351 92.173,106.153 93.406,104.92 93.406,104.606
AGND on Top Layer "AGND_L01_P079" (solid, remove dead copper, pour order 79): 99.376,79.812 99.406,79.782 99.406,78.13 100.145,78.13 100.532,78.13 101.038,78.635 101.038,79.346 100.573,79.812
AGND on Top Layer "AGND_L01_P078" (solid, remove dead copper, pour order 78): 106.872,89.771 106.468,89.366 106.468,87.923 107.033,87.358 108.43,87.358 108.811,87.739 108.811,89.517 108.557,89.771
+3V3 on Top Layer "+3V3_L01_P018" (solid, remove dead copper, pour order 18): 106.64,80.734 107.021,80.734 107.148,80.607 107.148,80.099 107.275,79.972 109.307,79.972 109.942,79.337 109.942,74.083 109.645,73.786 107.964,73.786 107.783,73.966 107.783,78.067 107.656,78.067 107.021,78.702 106.767,78.702 106.64,78.829
+2.5VA_REF on Top Layer "+2.5VA_REF_L01_P023" (solid, remove dead copper, pour order 23): 106.64,85.052 107.148,85.56 111.466,85.56 112.482,84.544 114.895,84.544 115.022,84.417 117.308,84.417 117.435,84.29 117.435,83.782 117.308,83.655 112.101,83.655 112.038,83.592 111.974,83.655 109.307,83.655 109.053,83.909 107.275,83.909 106.64,83.274
NetR18_1 on Top Layer "NETR18_1_L01_P024" (solid, remove dead copper, pour order 24): 117.435,83.02 117.308,83.147 112.99,83.147 112.863,83.02 112.863,82.258 112.99,82.131 114.26,82.131 114.514,82.385 117.308,82.385 117.435,82.512
AGND on Top Layer "AGND_L01_P033" (solid, remove dead copper, pour order 33): 112.703,87.211 112.298,86.807 112.298,85.363 112.863,84.798 114.26,84.798 114.641,85.179 114.641,86.957 114.387,87.211
AGND on Top Layer "AGND_L01_P034" (solid, remove dead copper, pour order 34): 107.656,82.893 108.037,83.274 109.18,83.274 109.688,82.766 109.688,80.48 109.561,80.353 107.783,80.353 107.656,80.48
+5VA on Top Layer "+5VA_L01_P077" (solid, remove dead copper, pour order 77): 78.679,96.594 78.694,96.609 80.331,96.609 81.329,95.611 82.477,95.611 82.779,95.309 82.779,94.232 82.642,94.096 81.752,94.096 81.587,94.261 78.866,94.261 78.686,94.44
AGND on Top Layer "AGND_L01_P076" (solid, remove dead copper, pour order 76): 78.649,93.702 78.661,93.702 78.807,93.848 78.819,93.837 82.361,93.837 82.857,93.341 82.857,92.235 82.722,92.1 78.796,92.1 78.615,92.28
AGND on Top Layer "AGND_L01_P075" (solid, remove dead copper, pour order 75): 93.028,93.906 93.038,93.896 94.454,93.896 94.454,93.886 94.562,93.778 94.484,93.699 94.484,90.158 94.405,90.079 93.077,90.079 92.841,90.315 92.841,93.778
+3V3 on Top Layer "+3V3_L01_P016" (solid, remove dead copper, pour order 16): 97.007,79.491 98.404,79.491 98.531,79.364 98.531,77.967 98.658,77.84 99.928,77.84 100.055,77.713 100.055,76.697 99.674,76.316 97.134,76.316 96.88,76.57 96.88,79.364
NetC32_2 on Top Layer "NETC32_2_L01_P044" (solid, remove dead copper, pour order 44): 80.585,85.144 79.803,84.362 79.803,84.004 79.799,84.001 80.561,84.001 81.45,83.112 82.339,83.112 82.339,84.56 81.755,85.144
AGND on Top Layer "AGND_L01_P045" (solid, remove dead copper, pour order 45): 80.561,86.541 80.18,86.16 80.18,85.779 80.434,85.525 82.593,85.525 82.847,85.779 82.847,86.287 82.593,86.541
AGND on Top Layer "AGND_L01_P047" (solid, remove dead copper, pour order 47): 85.304,82.814 85.514,82.604 85.514,82.223 85.26,81.969 83.482,81.969 83.482,82.814
+3V3 on Top Layer "+3V3_L01_P048" (solid, remove dead copper, pour order 48): 91.483,73.079 91.864,72.698 91.864,70.285 91.356,69.777 90.086,69.777 89.578,70.285 89.578,72.444 90.213,73.079
AGND on Top Layer "AGND_L01_P049" (solid, remove dead copper, pour order 49): 88.943,73.206 89.324,72.825 89.324,71.301 89.07,71.047 87.927,71.047 87.673,71.301 87.673,72.825 88.054,73.206
+3V3 on Top Layer "+3V3_L01_P050" (solid, remove dead copper, pour order 50): 82.212,81.969 82.593,81.588 82.593,79.81 82.339,79.556 79.799,79.556 79.545,79.81 79.545,81.334 80.18,81.969
AGND on Top Layer "AGND_L01_P051" (solid, remove dead copper, pour order 51): 79.799,79.302 79.545,79.048 79.545,77.524 79.799,77.27 82.085,77.27 82.339,77.524 82.339,78.921 81.958,79.302
AGND on Top Layer "AGND_L01_P053" (solid, remove dead copper, pour order 53): 84.244,79.429 83.736,78.921 83.736,76.762 84.879,76.762 84.879,77.524 85.133,77.778 85.895,77.778 86.149,78.032 86.149,79.175 85.895,79.429
+3V3 on Top Layer "+3V3_L01_P054" (solid, remove dead copper, pour order 54): 86.403,79.175 87.165,79.937 89.451,79.937 89.578,79.81 89.578,78.794 89.451,78.794 88.562,77.905 88.562,76.889 88.435,76.762 87.419,76.762 87.292,76.889 87.292,77.524 86.911,77.905 86.53,77.905 86.403,78.032
AGND on Top Layer "AGND_L01_P055" (solid, remove dead copper, pour order 55): 84.752,75.111 84.879,74.984 84.879,73.841 84.498,73.46 82.339,73.46 82.212,73.587 82.085,73.587 82.085,74.349 82.339,74.603 83.355,74.603 83.863,75.111
+3V3 on Top Layer "+3V3_L01_P056" (solid, remove dead copper, pour order 56): 80.053,76 81.577,76 81.704,75.873 81.704,74.476 81.831,74.349 81.831,73.714 81.577,73.46 80.053,73.46 79.672,73.841 79.672,75.619
+3V3 on Top Layer "+3V3_L01_P057" (solid, remove dead copper, pour order 57): 87.546,69.396 87.673,69.269 87.673,69.142 87.546,69.015 85.514,69.015 85.387,68.888 84.371,68.888 84.244,68.761 83.228,68.761 82.847,69.142 82.847,70.285 83.482,70.92 85.387,70.92 85.895,70.412 85.895,69.904 86.403,69.396
AGND on Top Layer "AGND_L01_P059" (solid, remove dead copper, pour order 59): 82.828,68.626 83.082,68.372 84.098,68.372 84.225,68.245 84.225,67.356 84.352,67.229 85.876,67.229 86.638,67.991 87.527,67.991 87.654,67.864 87.654,66.594 87.273,66.213 82.32,66.213 81.939,66.594 81.939,68.245 82.32,68.626
+5VA on Top Layer "+5VA_L01_P073" (solid, remove dead copper, pour order 73): 94.282,102.783 94.288,102.789 95.289,102.789 95.688,102.39 96.001,102.39 96.388,102.003 96.388,100.854 96.205,100.672 94.379,100.672 94.288,100.727
AGND on Top Layer "AGND_L01_P072" (solid, remove dead copper, pour order 72): 94.357,99.925 94.385,99.953 96.16,99.953 96.313,99.8 96.313,98.882 96.063,98.633 94.646,98.633 94.34,98.939
AGND on Top Layer "AGND_L01_P026" (solid, remove dead copper, pour order 26): 119.455,96.08 124.408,96.08 124.662,95.826 124.662,94.429 124.408,94.175 123.011,94.175 122.884,94.302 122.884,95.064 122.63,95.318 120.979,95.318 120.725,95.572 120.217,95.572
+5V on Top Layer "+5V_L01_P032" (solid, remove dead copper, pour order 32): 119.388,97.027 120.09,97.729 120.09,97.731 122.249,97.731 122.503,97.477 122.503,96.588 122.376,96.461 119.328,96.461 119.328,96.969
+5V on Top Layer "+5V_L01_P031" (solid, remove dead copper, pour order 31): 119.328,95.191 120.725,95.191 120.852,95.064 122.249,95.064 122.376,94.937 122.376,93.921 122.122,93.667 119.582,93.667 119.328,93.921
-5VA on Top Layer "-5VA_L01_P027" (solid, remove dead copper, pour order 27): 102.831,96.294 104.763,96.294 105.323,96.854 105.323,97.926 106.204,98.807 106.768,98.807 106.895,98.68 106.895,94.87 106.641,94.616 105.158,94.616 104.014,95.76 102.831,95.76
AGND on Top Layer "AGND_L01_P028" (solid, remove dead copper, pour order 28): 102.743,102.108 102.489,101.854 102.489,101.092 102.616,100.965 103.759,100.965 106.68,100.965 106.807,101.092 106.807,101.854 106.553,102.108
+2.5VA_VDD on Top Layer "+2.5VA_VDD_L01_P022" (solid, remove dead copper, pour order 22): 106.1,83.86 106.132,83.893 106.132,86.068 107.148,87.084 108.672,87.084 113.239,91.651 113.239,93.822 114.845,95.428 117.855,95.428 118.07,95.212 118.07,91.912 117.84,91.682 114.876,91.682 109.39,86.195 106.894,86.195 106.362,85.663 106.362,83.856
AGND on Top Layer "AGND_L01_P021" (solid, remove dead copper, pour order 21): 109.371,98.299 108.736,98.934 107.466,98.934 107.339,98.807 107.339,94.743 107.72,94.362 108.863,94.362 109.371,94.87
AGND on Top Layer "AGND_L01_P019" (solid, remove dead copper, pour order 19): 103.211,87.465 104.1,87.465 104.481,87.084 104.481,85.433 104.989,84.925 105.243,84.925 105.37,84.798 105.37,83.147 105.243,83.02 103.084,83.02 102.703,83.401 102.703,86.957
+3V3 on Top Layer "+3V3_L01_P015" (solid, remove dead copper, pour order 15): 108.839,103.378 110.49,103.378 111.379,104.267 114.027,104.267 114.433,103.862 114.433,103.384 114.046,102.997 109.22,102.997
+5VA on Top Layer "+5VA_L01_P010" (solid, remove dead copper, pour order 10): 98.806,93.599 98.806,93.218 98.679,93.091 97.028,93.091 96.774,92.837 96.774,89.662 96.497,89.385 95.713,89.385 95.123,89.975 95.123,93.726 95.377,93.98 98.425,93.98
AGND on Top Layer "AGND_L01_P002" (solid, remove dead copper, pour order 2): 77.53,102.494 78.165,101.859 78.165,100.208 77.784,99.827 76.133,99.827 75.308,100.652 75.308,101.669 76.133,102.494
-5VA on Top Layer "-5VA_L01_P001" (solid, remove dead copper, pour order 1): 78.419,101.732 79.308,102.621 80.705,102.621 81.34,101.986 81.34,100.97 80.197,99.827 79.562,99.827 79.054,99.319 79.054,98.176 78.927,98.049 78.673,98.049 78.546,98.176 78.546,99.065 78.419,99.192
AGND on Top Layer "AGND_L01_P000" (solid, remove dead copper, pour order 0): 69.656,102.24 69.275,101.859 69.275,99.7 69.529,99.446 70.926,99.446 71.053,99.573 71.053,101.986 70.799,102.24
+3V3 on Bottom Layer "+3V3_L04_P074" (solid, remove dead copper, pour order 74): 112.778,104.119 112.492,103.833 112.492,103.275 112.7,103.066 114.263,103.066 114.525,103.328 114.525,103.93 114.331,104.124 114.205,104.124
+3V3 on Power (split plane): 134.697,60.023 134.698,60.007 134.689,59.806 134.661,59.59 134.614,59.378 134.549,59.171 134.465,58.97 134.365,58.777 134.248,58.594 134.116,58.421 133.969,58.261 133.809,58.114 133.636,57.982 133.453,57.865 133.26,57.765 133.059,57.681 132.852,57.616 132.64,57.569 132.424,57.541 132.223,57.532 132.207,57.533 60.207,57.533 60.191,57.532 59.99,57.541 59.774,57.569 59.562,57.616 59.355,57.681 59.154,57.765 58.961,57.865 58.778,57.982 58.605,58.114 58.445,58.261 58.298,58.421 58.166,58.594 58.049,58.777 57.949,58.97 57.865,59.171 57.8,59.378 57.753,59.59 57.725,59.806 57.716,60.007 57.717,60.023 57.717,86.739 96.72,86.739 101.448,82.011 101.49,81.983 101.539,81.973 108.985,81.973 111.758,79.201 111.758,76.792 111.767,76.742 111.795,76.7 113.699,74.797 113.741,74.769 113.791,74.759 124.104,74.759 124.154,74.769 124.196,74.797 126.216,76.817 126.244,76.859 126.254,76.909 126.254,84.845 128.275,86.866 134.697,86.866
-5VA on Power (split plane): 132.424,116.505 132.64,116.477 132.852,116.43 133.059,116.365 133.26,116.281 133.453,116.181 133.636,116.064 133.809,115.932 133.969,115.785 134.116,115.625 134.248,115.452 134.365,115.269 134.465,115.076 134.549,114.875 134.614,114.668 134.661,114.456 134.689,114.24 134.698,114.039 134.697,114.023 134.697,102.491 125.605,102.491 125.555,102.482 125.513,102.454 123.138,100.079 116.151,100.079 116.102,100.069 116.06,100.041 110.979,94.961 110.255,94.236 101.908,94.236 98.3,97.844 98.3,101.038 100.168,102.905 100.196,102.947 100.205,102.997 100.205,105.029 100.196,105.079 100.168,105.121 99.152,106.137 99.11,106.165 99.06,106.174 97.282,106.174 97.232,106.165 97.19,106.137 96.301,105.248 94.818,103.764 94.478,103.782 94.475,103.781 94.472,103.782 91.678,103.782 91.672,103.781 86.192,103.781 86.142,103.771 86.1,103.743 80.209,97.852 77.203,97.852 77.153,97.842 77.111,97.814 72.904,93.607 57.717,93.607 57.717,114.023 57.716,114.039 57.725,114.24 57.753,114.456 57.8,114.668 57.865,114.875 57.949,115.076 58.049,115.269 58.166,115.452 58.298,115.625 58.445,115.785 58.605,115.932 58.778,116.064 58.961,116.181 59.154,116.281 59.355,116.365 59.562,116.43 59.774,116.477 59.99,116.505 60.191,116.514 60.207,116.513 132.207,116.513 132.223,116.514
+5VA on Power (split plane): 99.947,104.975 99.947,103.051 98.079,101.184 98.051,101.142 98.042,101.092 98.042,97.79 98.051,97.74 98.079,97.698 101.762,94.015 101.804,93.987 101.854,93.978 110.309,93.978 110.359,93.987 110.401,94.015 111.163,94.777 116.205,99.82 118.436,99.82 118.436,93.921 118.446,93.871 118.474,93.829 119.49,92.813 119.532,92.785 119.582,92.775 123.681,92.775 123.719,92.783 123.864,92.783 123.9,92.776 123.987,92.776 124.037,92.786 124.079,92.814 128.315,97.05 134.697,97.05 134.697,87.124 128.221,87.124 128.172,87.115 128.13,87.087 126.033,84.99 126.005,84.948 125.995,84.899 125.995,76.962 124.051,75.018 113.844,75.018 112.016,76.845 112.016,79.255 112.007,79.304 111.979,79.346 109.13,82.194 109.088,82.222 109.039,82.232 101.593,82.232 96.866,86.96 96.824,86.988 96.774,86.997 57.717,86.997 57.717,93.348 72.958,93.348 73.007,93.358 73.049,93.386 77.256,97.593 80.263,97.593 80.313,97.603 80.355,97.631 86.246,103.522 91.794,103.522 91.8,103.523 94.468,103.523 94.862,103.503 94.866,103.503 94.869,103.503 94.891,103.507 94.912,103.51 94.915,103.512 94.919,103.512 94.937,103.525 94.956,103.536 94.958,103.539 94.961,103.54 96.485,105.064 97.336,105.916 99.006,105.916
+5V on Power (split plane): 134.697,97.309 128.335,97.309 128.326,97.314 128.277,97.324 128.227,97.314 128.185,97.286 128.17,97.271 128.169,97.271 128.169,97.27 123.939,93.04 123.929,93.042 123.705,93.042 123.666,93.034 119.635,93.034 118.695,93.975 118.695,99.82 123.192,99.82 123.241,99.829 123.283,99.858 125.658,102.233 134.697,102.233
AGND on GND1 (split plane): 132.424,116.505 132.64,116.477 132.852,116.43 133.059,116.365 133.26,116.281 133.453,116.181 133.636,116.064 133.809,115.932 133.969,115.785 134.116,115.625 134.248,115.452 134.365,115.269 134.465,115.076 134.549,114.875 134.614,114.668 134.661,114.456 134.689,114.24 134.698,114.039 134.697,114.023 134.697,60.023 134.698,60.007 134.689,59.806 134.661,59.59 134.614,59.378 134.549,59.171 134.465,58.97 134.365,58.777 134.248,58.594 134.116,58.421 133.969,58.261 133.809,58.114 133.636,57.982 133.453,57.865 133.26,57.765 133.059,57.681 132.852,57.616 132.64,57.569 132.424,57.541 132.223,57.532 132.207,57.533 60.207,57.533 60.191,57.532 59.99,57.541 59.774,57.569 59.562,57.616 59.355,57.681 59.154,57.765 58.961,57.865 58.778,57.982 58.605,58.114 58.445,58.261 58.298,58.421 58.166,58.594 58.049,58.777 57.949,58.97 57.865,59.171 57.8,59.378 57.753,59.59 57.725,59.806 57.716,60.007 57.717,60.023 57.717,114.023 57.716,114.039 57.725,114.24 57.753,114.456 57.8,114.668 57.865,114.875 57.949,115.076 58.049,115.269 58.166,115.452 58.298,115.625 58.445,115.785 58.605,115.932 58.778,116.064 58.961,116.181 59.154,116.281 59.355,116.365 59.562,116.43 59.774,116.477 59.99,116.505 60.191,116.514 60.207,116.513 132.207,116.513 132.223,116.514

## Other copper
Power (plane layer: these items are gaps in the copper):
  lines w0.254: 57.277,85.598 57.277,86.868 69.215,86.868 73.533,86.868 90.424,86.868 96.774,86.868 101.539,82.103 109.039,82.103 111.887,79.255 111.887,76.792 113.791,74.888 124.104,74.888 126.125,76.909 126.125,84.899 128.221,86.995 135.128,86.995 ; 57.337,93.477 72.958,93.477 77.203,97.722 80.263,97.722 86.192,103.651 91.794,103.651 ; 91.678,103.652 94.472,103.652 94.869,103.632 96.393,105.156 97.282,106.045 99.06,106.045 100.076,105.029 100.076,102.997 98.171,101.092 98.171,97.79 101.854,94.107 104.267,94.107 110.309,94.107 111.071,94.869 116.151,99.949 123.192,99.949 125.605,102.362 135.255,102.362 ; 118.566,99.947 118.566,93.921 119.582,92.905 123.681,92.905 ; 123.705,92.913 123.929,92.913 ; 123.9,92.905 123.987,92.905 128.277,97.195 ; 128.261,97.179 135.5,97.179

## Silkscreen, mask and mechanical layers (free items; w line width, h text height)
Top Overlay:
  drawing of 3721 lines, arcs and shapes, not listed
Mechanical 1:
  the board outline again, w1.016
